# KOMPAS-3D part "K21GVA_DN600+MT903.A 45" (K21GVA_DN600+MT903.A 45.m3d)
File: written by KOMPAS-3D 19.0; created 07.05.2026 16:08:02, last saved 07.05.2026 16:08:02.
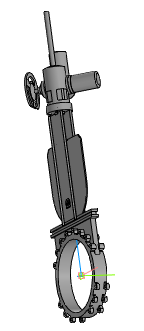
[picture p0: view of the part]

Document properties: Автор: Энергия; Полное имя файла: ..\K21GVA_DN50-DN1000+MT903.A\K21GVA_DN600+MT903.A 45.a3d

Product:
- Part/product: K21GVA_DN600+MT903.A 45
    Масса: 367.224

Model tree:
1. Операция без истории:1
